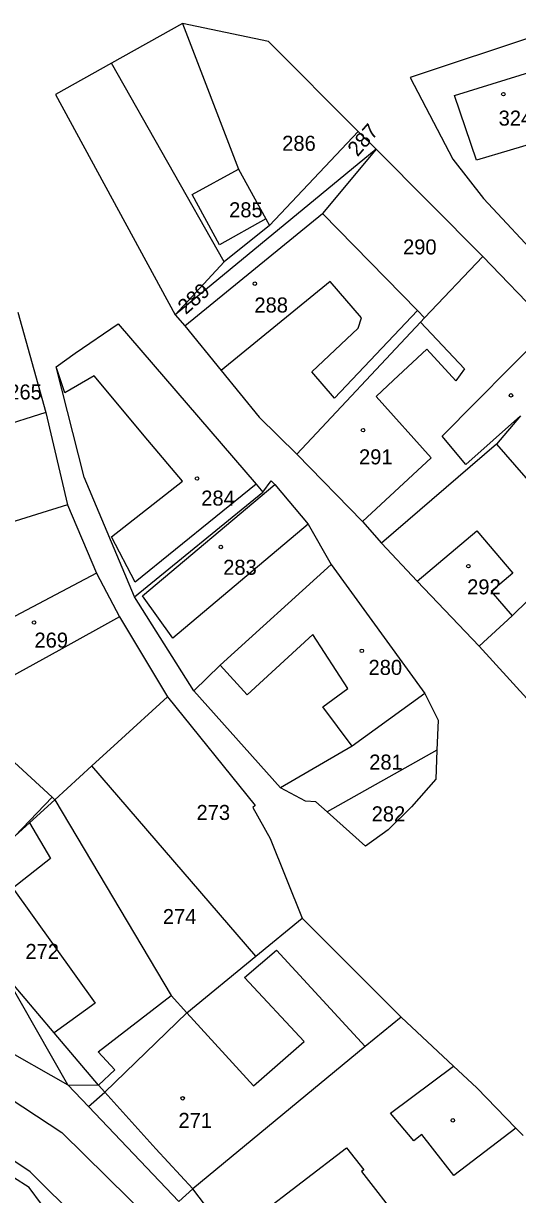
# Model space of a CAD drawing. Extents: x -563148 to -561712, y -1182311 to -1179502.
# Drawn here: x -562585.8 to -562536.5, y -1180433.7 to -1180316.9 of the extents above; entities that cross this region are included whole.
import ezdxf

# ---------------------------------------------------------------- set-up
doc = ezdxf.new("R2010")
doc.units = 0
for name, color, linetype in [('Vrstva 55', 7, 'Continuous'), ('Vrstva 56', 7, 'Continuous'), ('Vrstva 57', 7, 'Continuous')]:
    doc.layers.add(name, color=color, linetype=linetype)

msp = doc.modelspace()

# ---------------------------------------------------------------- linework, layer by layer
at = {"layer": 'Vrstva 55'}
for p, q in [((-562569.9, -1180316.91), (-562576.97, -1180320.87)), ((-562569.9, -1180316.91), (-562564.3, -1180331.43)), ((-562561.34, -1180318.72), (-562569.9, -1180316.91)), ((-562534.29, -1180318.01), (-562547.2, -1180322.31)), ((-562552.37, -1180327.69), (-562561.34, -1180318.72)), ((-562576.97, -1180320.87), (-562582.57, -1180324)), ((-562547.2, -1180322.31), (-562542.94, -1180330.43)), ((-562582.57, -1180324), (-562570.62, -1180345.96)), ((-562552.37, -1180327.69), (-562561.24, -1180337.05)), ((-562550.6, -1180329.45), (-562552.37, -1180327.69)), ((-562550.6, -1180329.45), (-562570.62, -1180345.96)), ((-562550.6, -1180329.45), (-562555.93, -1180335.85)), ((-562539.96, -1180340.15), (-562550.6, -1180329.45)), ((-562542.94, -1180330.43), (-562539.89, -1180334.36)), ((-562564.3, -1180331.43), (-562561.6, -1180336.39)), ((-562539.89, -1180334.36), (-562533.25, -1180341.5)), ((-562569.68, -1180347.06), (-562555.93, -1180335.85)), ((-562561.6, -1180336.39), (-562561.24, -1180337.05)), ((-562555.93, -1180335.85), (-562546.46, -1180345.54)), ((-562561.24, -1180337.05), (-562565.74, -1180340.68)), ((-562539.96, -1180340.15), (-562545.76, -1180346.25)), ((-562533.21, -1180347.15), (-562539.96, -1180340.15)), ((-562565.74, -1180340.68), (-562570.62, -1180345.96)), ((-562586.32, -1180345.68), (-562583.53, -1180355.7)), ((-562570.62, -1180345.96), (-562569.68, -1180347.06)), ((-562546.46, -1180345.54), (-562545.76, -1180346.25)), ((-562545.76, -1180346.25), (-562546.17, -1180346.68)), ((-562580.61, -1180349.79), (-562576.32, -1180346.87)), ((-562576.32, -1180346.87), (-562562.57, -1180362.84)), ((-562569.68, -1180347.06), (-562566.04, -1180351.51)), ((-562546.17, -1180346.68), (-562558.5, -1180359.84)), ((-562582.49, -1180351.13), (-562580.61, -1180349.79)), ((-562579.71, -1180362.13), (-562582.49, -1180351.13)), ((-562566.04, -1180351.51), (-562562.27, -1180356.15)), ((-562583.53, -1180355.7), (-562593.77, -1180358.93)), ((-562583.53, -1180355.7), (-562581.36, -1180364.91)), ((-562562.27, -1180356.15), (-562558.5, -1180359.84)), ((-562536.21, -1180356.03), (-562538.59, -1180358.87)), ((-562538.59, -1180358.87), (-562550.07, -1180368.72)), ((-562538.59, -1180358.87), (-562532.86, -1180365.45)), ((-562558.5, -1180359.84), (-562551.95, -1180366.56)), ((-562574.67, -1180374.09), (-562579.71, -1180362.13)), ((-562561.9, -1180363.64), (-562561.06, -1180362.51)), ((-562561.06, -1180362.51), (-562560.7, -1180362.88)), ((-562574.67, -1180374.09), (-562561.9, -1180363.64)), ((-562562.57, -1180362.84), (-562561.9, -1180363.64)), ((-562560.7, -1180362.88), (-562557.38, -1180366.82)), ((-562581.36, -1180364.91), (-562588.11, -1180366.98)), ((-562581.36, -1180364.91), (-562578.48, -1180371.71)), ((-562557.38, -1180366.82), (-562555.08, -1180370.84)), ((-562551.95, -1180366.56), (-562550.07, -1180368.72)), ((-562550.07, -1180368.72), (-562546.5, -1180372.51)), ((-562578.48, -1180371.71), (-562590.54, -1180378.08)), ((-562578.48, -1180371.71), (-562576.17, -1180376.07)), ((-562566.14, -1180380.89), (-562555.08, -1180370.84)), ((-562555.08, -1180370.84), (-562545.73, -1180383.72)), ((-562546.5, -1180372.51), (-562540.33, -1180378.98)), ((-562532.99, -1180372), (-562537.03, -1180375.97)), ((-562568.76, -1180383.46), (-562574.67, -1180374.09)), ((-562576.17, -1180376.07), (-562571.39, -1180384.05)), ((-562537.03, -1180375.97), (-562540.33, -1180378.98)), ((-562540.33, -1180378.98), (-562531.73, -1180388.46)), ((-562568.76, -1180383.46), (-562566.14, -1180380.89)), ((-562560.12, -1180393.11), (-562568.76, -1180383.46)), ((-562571.39, -1180384.05), (-562576.34, -1180388.56)), ((-562571.39, -1180384.05), (-562562.66, -1180394.89)), ((-562545.73, -1180383.72), (-562552.98, -1180388.97)), ((-562545.73, -1180383.72), (-562544.42, -1180386.36)), ((-562582.91, -1180394.04), (-562592.39, -1180385.34)), ((-562544.42, -1180386.36), (-562544.54, -1180389.36)), ((-562576.34, -1180388.56), (-562578.93, -1180390.93)), ((-562552.98, -1180388.97), (-562560.12, -1180393.11)), ((-562544.54, -1180389.36), (-562555.48, -1180395.51)), ((-562544.54, -1180389.36), (-562544.65, -1180392.25)), ((-562578.93, -1180390.93), (-562582.63, -1180394.3)), ((-562562.6, -1180409.91), (-562578.93, -1180390.93)), ((-562544.65, -1180392.25), (-562547.05, -1180395.01)), ((-562582.63, -1180394.3), (-562582.91, -1180394.04)), ((-562557.64, -1180394.43), (-562560.12, -1180393.11)), ((-562582.63, -1180394.3), (-562585.15, -1180396.6)), ((-562582.63, -1180394.3), (-562571.04, -1180413.83)), ((-562562.66, -1180394.89), (-562562.89, -1180395.08)), ((-562562.89, -1180395.08), (-562561.15, -1180398.18)), ((-562556.6, -1180394.52), (-562557.64, -1180394.43)), ((-562555.48, -1180395.51), (-562556.6, -1180394.52)), ((-562547.05, -1180395.01), (-562549.39, -1180397.3)), ((-562551.64, -1180398.92), (-562555.48, -1180395.51)), ((-562585.15, -1180396.6), (-562586.62, -1180397.95)), ((-562549.39, -1180397.3), (-562551.64, -1180398.92)), ((-562561.15, -1180398.18), (-562557.96, -1180406.1)), ((-562585.19, -1180432.97), (-562629.01, -1180405.44)), ((-562562.6, -1180409.91), (-562557.96, -1180406.1)), ((-562557.96, -1180406.1), (-562548.09, -1180415.97)), ((-562569.47, -1180415.55), (-562562.6, -1180409.91)), ((-562581.34, -1180422.73), (-562587.57, -1180411.77)), ((-562571.04, -1180413.83), (-562569.47, -1180415.55)), ((-562577.64, -1180423.46), (-562569.47, -1180415.55)), ((-562548.09, -1180415.97), (-562551.68, -1180418.89)), ((-562542.87, -1180420.86), (-562548.09, -1180415.97)), ((-562590.39, -1180417.59), (-562581.34, -1180422.73)), ((-562551.68, -1180418.89), (-562568.86, -1180433.08)), ((-562540.54, -1180423.04), (-562542.87, -1180420.86)), ((-562581.34, -1180422.73), (-562579.28, -1180424.9)), ((-562536.65, -1180427.04), (-562540.54, -1180423.04)), ((-562579.28, -1180424.9), (-562577.64, -1180423.46)), ((-562579.28, -1180424.9), (-562570.28, -1180434.36)), ((-562535.94, -1180427.77), (-562536.65, -1180427.04)), ((-562560.24, -1180466.47), (-562585.19, -1180432.97)), ((-562568.86, -1180433.08), (-562570.28, -1180434.36))]:
    msp.add_line(p, q, dxfattribs=at)
at = {"layer": 'Vrstva 56'}
for p, q in [((-562542.79, -1180324.11), (-562528.05, -1180319.54)), ((-562565.74, -1180340.68), (-562576.97, -1180320.87)), ((-562540.57, -1180330.55), (-562542.79, -1180324.11)), ((-562529.18, -1180327.13), (-562540.57, -1180330.55)), ((-562568.95, -1180333.97), (-562564.3, -1180331.43)), ((-562566.22, -1180338.98), (-562568.95, -1180333.97)), ((-562561.6, -1180336.39), (-562566.22, -1180338.98)), ((-562555.19, -1180342.64), (-562566.04, -1180351.51)), ((-562552.06, -1180346.27), (-562555.19, -1180342.64)), ((-562546.46, -1180345.54), (-562554.73, -1180354.26)), ((-562552.4, -1180347.29), (-562552.06, -1180346.27)), ((-562556.99, -1180351.63), (-562552.4, -1180347.29)), ((-562546.17, -1180346.68), (-562541.79, -1180351.36)), ((-562544.02, -1180358.05), (-562533.21, -1180347.15)), ((-562545.54, -1180349.4), (-562548.87, -1180352.48)), ((-562542.64, -1180352.53), (-562545.54, -1180349.4)), ((-562581.64, -1180353.73), (-562582.49, -1180351.13)), ((-562578.72, -1180352.04), (-562581.64, -1180353.73)), ((-562573.34, -1180358.44), (-562578.72, -1180352.04)), ((-562554.73, -1180354.26), (-562556.99, -1180351.63)), ((-562541.79, -1180351.36), (-562542.64, -1180352.53)), ((-562548.87, -1180352.48), (-562550.6, -1180354.09)), ((-562550.6, -1180354.09), (-562545.1, -1180360.21)), ((-562536.21, -1180356.03), (-562541.64, -1180360.89)), ((-562569.89, -1180362.54), (-562573.34, -1180358.44)), ((-562541.64, -1180360.89), (-562544.02, -1180358.05)), ((-562545.1, -1180360.21), (-562551.95, -1180366.56)), ((-562576.99, -1180368.08), (-562569.89, -1180362.54)), ((-562562.57, -1180362.84), (-562574.62, -1180372.62)), ((-562573.89, -1180373.99), (-562560.7, -1180362.88)), ((-562557.38, -1180366.82), (-562570.86, -1180378.2)), ((-562574.62, -1180372.62), (-562576.99, -1180368.08)), ((-562546.5, -1180372.51), (-562540.54, -1180367.5)), ((-562540.54, -1180367.5), (-562536.97, -1180371.7)), ((-562536.97, -1180371.7), (-562539.14, -1180373.53)), ((-562570.86, -1180378.2), (-562573.89, -1180373.99)), ((-562539.14, -1180373.53), (-562537.03, -1180375.97)), ((-562576.17, -1180376.07), (-562582.23, -1180379.42)), ((-562556.89, -1180377.84), (-562563.44, -1180383.83)), ((-562553.42, -1180383.2), (-562556.89, -1180377.84)), ((-562582.23, -1180379.42), (-562587.12, -1180382.13)), ((-562563.44, -1180383.83), (-562566.14, -1180380.89)), ((-562555.92, -1180385.05), (-562553.42, -1180383.2)), ((-562552.98, -1180388.97), (-562555.92, -1180385.05)), ((-562582.91, -1180394.04), (-562586.62, -1180397.95)), ((-562585.15, -1180396.6), (-562583.06, -1180400.16)), ((-562583.06, -1180400.16), (-562586.8, -1180403.11)), ((-562586.8, -1180403.11), (-562578.62, -1180414.59)), ((-562563.73, -1180412.04), (-562560.53, -1180409.29)), ((-562560.53, -1180409.29), (-562551.68, -1180418.89)), ((-562582.68, -1180417.55), (-562587.57, -1180411.77)), ((-562557.76, -1180418.4), (-562563.73, -1180412.04)), ((-562578.32, -1180419.45), (-562571.04, -1180413.83)), ((-562578.62, -1180414.59), (-562582.68, -1180417.55)), ((-562569.47, -1180415.55), (-562562.83, -1180422.83)), ((-562595.84, -1180418.36), (-562581.94, -1180427.49)), ((-562578.27, -1180422.76), (-562582.68, -1180417.55)), ((-562562.83, -1180422.83), (-562557.76, -1180418.4)), ((-562576.65, -1180421.22), (-562578.32, -1180419.45)), ((-562549.17, -1180425.56), (-562542.87, -1180420.86)), ((-562578.27, -1180422.76), (-562576.65, -1180421.22)), ((-562585.08, -1180431.4), (-562598.08, -1180422.83)), ((-562581.34, -1180422.73), (-562578.27, -1180422.76)), ((-562577.64, -1180423.46), (-562578.27, -1180422.76)), ((-562572.56, -1180429.12), (-562577.64, -1180423.46)), ((-562546.85, -1180428.3), (-562549.17, -1180425.56)), ((-562581.94, -1180427.49), (-562570.69, -1180438.52)), ((-562546.04, -1180427.67), (-562546.85, -1180428.3)), ((-562542.84, -1180431.76), (-562546.04, -1180427.67)), ((-562536.65, -1180427.04), (-562542.84, -1180431.76)), ((-562568.86, -1180433.08), (-562572.56, -1180429.12)), ((-562562.4, -1180435.8), (-562553.54, -1180429)), ((-562553.54, -1180429), (-562551.81, -1180431.2)), ((-562574.36, -1180442), (-562585.08, -1180431.4)), ((-562551.81, -1180431.2), (-562552.04, -1180431.38)), ((-562552.04, -1180431.38), (-562547.17, -1180437.63)), ((-562556.19, -1180449.71), (-562568.86, -1180433.08))]:
    msp.add_line(p, q, dxfattribs=at)
at = {"layer": 'Vrstva 57'}
for centre in [(-562537.91, -1180323.97), (-562562.68, -1180342.86), (-562537.14, -1180353.99), (-562551.9, -1180357.46), (-562568.45, -1180362.28), (-562566.07, -1180369.11), (-562541.4, -1180371.02), (-562584.7, -1180376.64), (-562552.02, -1180379.46), (-562569.88, -1180424.07), (-562542.94, -1180426.27)]:
    msp.add_circle(centre, 0.175, dxfattribs=at)

# ---------------------------------------------------------------- texts
for s, p in [('324', (-562538.38, -1180327.1)), ('286', (-562559.96, -1180329.61)), ('285', (-562565.25, -1180336.24)), ('290', (-562547.91, -1180339.94)), ('288', (-562562.73, -1180345.73)), ('265', (-562587.27, -1180354.4)), ('291', (-562552.3, -1180360.87)), ('284', (-562568.03, -1180364.98)), ('283', (-562565.84, -1180371.88)), ('292', (-562541.52, -1180373.83)), ('269', (-562584.66, -1180379.14)), ('280', (-562551.35, -1180381.86)), ('281', (-562551.28, -1180391.3)), ('273', (-562568.5, -1180396.32)), ('282', (-562551.04, -1180396.46)), ('274', (-562571.86, -1180406.7)), ('272', (-562585.56, -1180410.18)), ('271', (-562570.3, -1180427.02))]:
    msp.add_text(s, height=1.5, dxfattribs=at).set_placement(p)
for s, rotation, p in [('287', 48.9672, (-562552.45, -1180330.27)), ('289', 41.1569, (-562569.56, -1180345.99))]:
    msp.add_text(s, height=1.5, rotation=rotation, dxfattribs=at).set_placement(p)

doc.saveas('drawing.dxf')
